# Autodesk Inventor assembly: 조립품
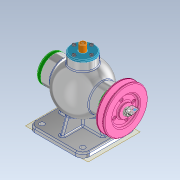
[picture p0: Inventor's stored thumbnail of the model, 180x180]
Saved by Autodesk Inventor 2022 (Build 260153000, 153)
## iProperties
Created: 2024-04
Part Number: 조립품
Document SubType Name: Assembly
Designer: admin
Author: admin
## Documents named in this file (16)
- C:\Users\admin\Desktop\740406V1008\조립품.iam
- C:\Users\admin\Desktop\740406V1008\본체.ipt
- C:\Users\admin\Desktop\740406V1008\뒤커버.ipt
- C:\Users\admin\Desktop\740406V1008\앞커버.ipt
- C:\Users\admin\Desktop\740406V1008\상부커버.ipt
- C:\Users\admin\Desktop\740406V1008\베어링- 6202.ipt
- KS B 2023 - 6202 - 15 x 35 x 11 - 7.8.ipt
- C:\Users\admin\Desktop\740406V1008\칼라.ipt
- C:\Users\admin\Desktop\740406V1008\편심축.ipt
- C:\Users\admin\Desktop\740406V1008\키 4 x 4 x 12.ipt
- C:\Users\admin\Desktop\740406V1008\오일실 15 30 7.ipt
- C:\Users\admin\Desktop\740406V1008\V-벨트풀리.ipt
- C:\Users\admin\Desktop\740406V1008\너트 M8.ipt
- C:\Users\admin\Desktop\740406V1008\볼트 M4 x 16.ipt
- C:\Users\admin\Desktop\740406V1008\볼트 M4 x 12.ipt
- C:\Users\admin\Desktop\740406V1008\슬라이드.ipt
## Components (15 placed, 4 different names)
1. KS B 2023 - 6202 - 15 x 35 x 11 - 7.8:1
2. KS B 2023 - 6202 - 15 x 35 x 11 - 7.8:2
3. V-벨트풀리:1
4. ISO 4762 M4 x 16:1
5. ISO 4762 M4 x 16:2
6. ISO 4762 M4 x 16:3
7. ISO 4762 M4 x 16:4
8. ISO 4762 M4 x 16:5
9. ISO 4762 M4 x 16:6
10. ISO 4762 M4 x 16:7
11. ISO 4762 M4 x 16:8
12. KS B 1021 - 에 따름 ISO 1207 - 미터 A  M 4 x 12:1
13. KS B 1021 - 에 따름 ISO 1207 - 미터 A  M 4 x 12:2
14. KS B 1021 - 에 따름 ISO 1207 - 미터 A  M 4 x 12:3
15. KS B 1021 - 에 따름 ISO 1207 - 미터 A  M 4 x 12:4
